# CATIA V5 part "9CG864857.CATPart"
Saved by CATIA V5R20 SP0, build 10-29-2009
Part number: 9CG864857
Revision: ANY
Definition: UNKNOWN
Nomenclature: 9CG864857
Source: Unknown
Bounding box of the stored display mesh (mm): x -35 to 51, y -33 to 32, z -24 to 24
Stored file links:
  C:\Users\Utente\Desktop\IO LAVORO\3D X SITO CF\CUMSA\3D files CG\CG 864857\9CG864857.CATPart
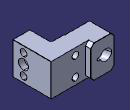
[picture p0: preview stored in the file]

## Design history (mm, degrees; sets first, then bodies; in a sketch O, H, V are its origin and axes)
Body1 "Cortar-Extruir3" (main body)
  Solid1: solid without history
